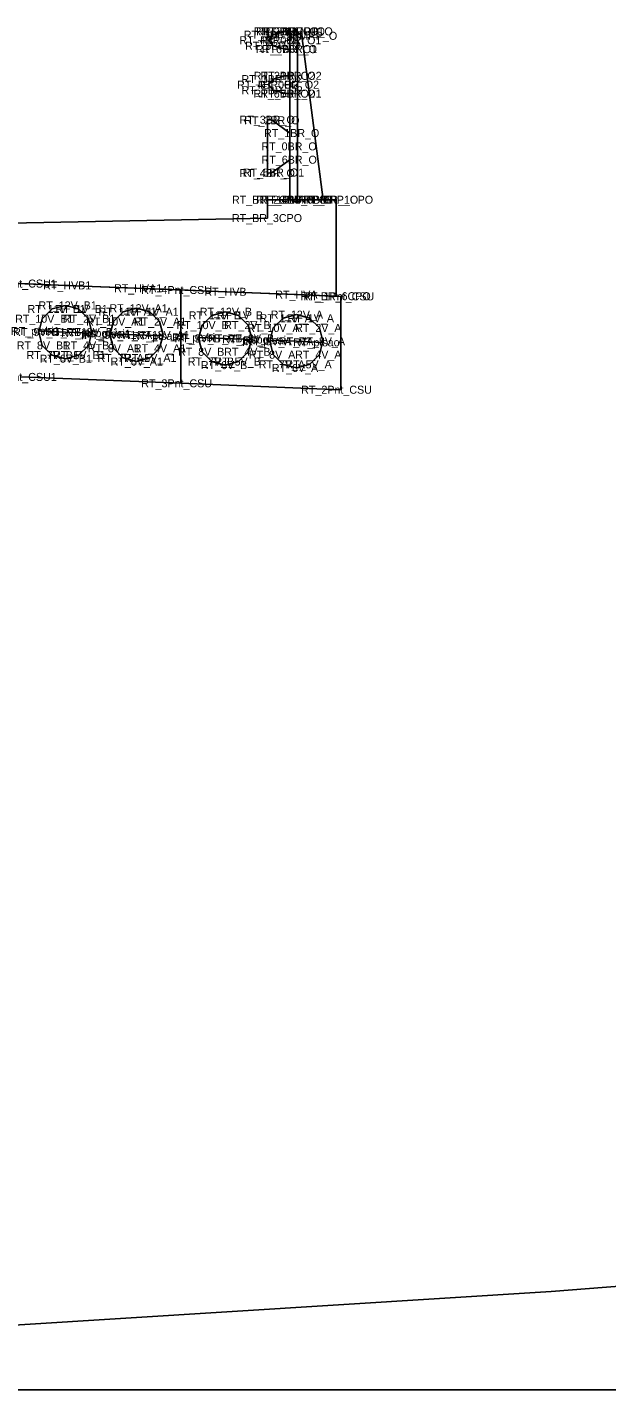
# Model space of a CAD drawing. Extents: x -26 to 1163, y -10 to 9537.
# Drawn here: x 99.37 to 110.24, y 6000 to 6025.54 of the extents above; entities that cross this region are included whole.
import ezdxf

# ---------------------------------------------------------------- set-up
doc = ezdxf.new("R2010")
doc.units = 0
for name, color, linetype in [('Exist Cross Section Cell', 7, 'Continuous'), ('Exist XS Ground Line', 7, 'Continuous'), ('Prop CMT Bridge Metal Rail', 7, 'Continuous'), ('Prop CMT Bridge Metal Rail Post', 7, 'Continuous'), ('Prop CMT Concrete Structures', 7, 'Continuous'), ('Prop CMT Corridor Surface Symbology Blue', 7, 'Continuous'), ('Scratch_Level_0', 7, 'Continuous')]:
    doc.layers.add(name, color=color, linetype=linetype)

msp = doc.modelspace()

# ---------------------------------------------------------------- linework, layer by layer
at = {"layer": 'Exist Cross Section Cell'}
msp.add_line((80, 6000), (160, 6000), dxfattribs=at)
at = {"layer": 'Exist XS Ground Line'}
msp.add_lwpolyline([(54.51, 6004.315), (62.713, 6003.678), (73.379, 6003.022), (80, 6002.975), (87.016, 6002.925), (91.312, 6001.299), (94.565, 6001.099), (97.121, 6001.084), (109.199, 6001.839), (119.662, 6002.66), (122.228, 6004.967), (124.251, 6006.909), (129.58, 6007.46), (132.249, 6006.951), (132.875, 6007.018), (147.194, 6007.634), (148.841, 6007.735), (150.67, 6007.781), (160, 6007.577)], dxfattribs=at)
at = {"layer": 'Prop CMT Bridge Metal Rail'}
for points in [[(104.293, 6025.465), (104.209, 6025.465), (103.98, 6025.402), (103.897, 6025.298)], [(104.293, 6025.298), (104.293, 6025.465)], [(103.897, 6025.298), (103.98, 6025.194), (104.209, 6025.132), (104.293, 6025.132)], [(104.293, 6025.132), (104.293, 6025.298)], [(104.293, 6024.632), (104.209, 6024.632), (103.98, 6024.569), (103.897, 6024.465)], [(103.897, 6024.465), (103.98, 6024.361), (104.209, 6024.298), (104.293, 6024.298)], [(104.293, 6024.465), (104.293, 6024.632)], [(104.293, 6024.298), (104.293, 6024.465)], [(104.293, 6023.559), (103.964, 6023.798), (103.876, 6023.809)], [(103.876, 6023.809), (103.876, 6022.809)], [(104.293, 6023.309), (104.293, 6023.559)], [(104.293, 6023.059), (104.293, 6023.309)], [(103.876, 6022.809), (103.964, 6022.819), (104.293, 6023.059)]]:
    msp.add_lwpolyline(points, dxfattribs=at)
at = {"layer": 'Prop CMT Bridge Metal Rail Post'}
for points in [[(104.293, 6022.309), (104.293, 6025.465)], [(104.293, 6025.465), (104.438, 6025.465)], [(104.438, 6025.465), (104.438, 6022.309)], [(104.438, 6025.465), (104.522, 6025.382), (104.918, 6022.309)]]:
    msp.add_lwpolyline(points, dxfattribs=at)
at = {"layer": 'Prop CMT Concrete Structures'}
for points in [[(98.375, 6020.772), (98.376, 6021.855), (103.875, 6021.965), (103.876, 6022.309), (105.166, 6022.309), (105.167, 6020.5)], [(105.167, 6020.5), (98.375, 6020.772)], [(99.25, 6020.737), (100.083, 6020.703), (101.417, 6020.65), (102.25, 6020.617)], [(102.25, 6020.617), (102.25, 6018.867)], [(102.25, 6020.617), (103.083, 6020.583), (104.417, 6020.53), (105.25, 6020.497)], [(102.25, 6018.867), (102.25, 6020.617)], [(99.583, 6019.828), (99.65, 6020.078), (99.833, 6020.261), (100.083, 6020.328)], [(100.083, 6020.328), (100.333, 6020.261), (100.516, 6020.078), (100.583, 6019.828)], [(105.25, 6020.497), (105.25, 6018.747)], [(100.917, 6019.775), (100.984, 6020.025), (101.167, 6020.208), (101.417, 6020.275)], [(101.417, 6020.275), (101.667, 6020.208), (101.85, 6020.025), (101.917, 6019.775)], [(102.583, 6019.708), (102.65, 6019.958), (102.833, 6020.141), (103.083, 6020.208)], [(103.083, 6020.208), (103.333, 6020.141), (103.516, 6019.958), (103.583, 6019.708)], [(103.917, 6019.655), (103.984, 6019.905), (104.167, 6020.088), (104.417, 6020.155)], [(104.417, 6020.155), (104.667, 6020.088), (104.85, 6019.905), (104.917, 6019.655)], [(100.583, 6019.828), (100.516, 6019.578), (100.333, 6019.395), (100.083, 6019.328), (99.833, 6019.395), (99.65, 6019.578), (99.583, 6019.828)], [(101.917, 6019.775), (101.85, 6019.525), (101.667, 6019.342), (101.417, 6019.275), (101.167, 6019.342), (100.984, 6019.525), (100.917, 6019.775)], [(103.583, 6019.708), (103.516, 6019.458), (103.333, 6019.275), (103.083, 6019.208), (102.833, 6019.275), (102.65, 6019.458), (102.583, 6019.708)], [(104.917, 6019.655), (104.85, 6019.405), (104.667, 6019.222), (104.417, 6019.155), (104.167, 6019.222), (103.984, 6019.405), (103.917, 6019.655)], [(102.25, 6018.867), (99.25, 6018.987)], [(105.25, 6018.747), (102.25, 6018.867)]]:
    msp.add_lwpolyline(points, dxfattribs=at)
at = {"layer": 'Prop CMT Corridor Surface Symbology Blue'}
for points in [[(99.593, 6019.848), (100.083, 6019.828), (100.573, 6019.809)], [(100.927, 6019.795), (101.417, 6019.775), (101.907, 6019.755)], [(102.593, 6019.728), (103.083, 6019.708), (103.573, 6019.689)], [(103.927, 6019.675), (104.417, 6019.655), (104.907, 6019.635)]]:
    msp.add_lwpolyline(points, dxfattribs=at)

# ---------------------------------------------------------------- texts
at = {"layer": 'Scratch_Level_0'}
for s, p in [('RT_3BR_O1', (103.431, 6025.327)), ('RT_2BMRP_O', (103.617, 6025.39)), ('RT_2BR_O1', (103.66, 6025.39)), ('RT_3BMRP_O', (103.763, 6025.39)), ('RT_1BR_O1', (103.786, 6025.39)), ('RT_5BMRP_O', (103.846, 6025.307)), ('RT_4BR_O1', (103.348, 6025.223)), ('RT_5BR_O', (103.456, 6025.119)), ('RT_6BR_O1', (103.657, 6025.057)), ('RT_0BR_O1', (103.738, 6025.223)), ('RT_7BR_O', (103.768, 6025.057)), ('RT_3BR_O2', (103.388, 6024.494)), ('RT_2BR_O2', (103.618, 6024.557)), ('RT_1BR_O2', (103.743, 6024.557)), ('RT_4BR_O2', (103.305, 6024.39)), ('RT_5BR_O2', (103.388, 6024.286)), ('RT_0BR_O2', (103.695, 6024.39)), ('RT_6BR_O2', (103.614, 6024.223)), ('RT_7BR_O1', (103.743, 6024.223)), ('RT_3BR_O', (103.352, 6023.734)), ('RT_2BR_O', (103.44, 6023.723)), ('RT_1BR_O', (103.811, 6023.484)), ('RT_0BR_O', (103.762, 6023.234)), ('RT_6BR_O', (103.765, 6022.984)), ('RT_4BR_O', (103.352, 6022.734)), ('RT_5BR_O1', (103.415, 6022.744)), ('RT_BR_2CPO', (103.21, 6022.234)), ('RT_1BMRP_O', (103.66, 6022.234)), ('RT_4BMRP_O', (103.763, 6022.234)), ('RT_6BMRP_O', (104.239, 6022.234)), ('RT_BR_1CPO', (104.542, 6022.234)), ('RT_BR_3CPO', (103.209, 6021.89)), ('RT_4Pnt_CSU1', (98.483, 6020.662)), ('RT_HVB1', (99.666, 6020.628)), ('RT_HVA1', (100.997, 6020.575)), ('RT_4Pnt_CSU', (101.508, 6020.542)), ('RT_HVB', (102.691, 6020.508)), ('RT_HVA', (104.022, 6020.455)), ('RT_BR_6CPO', (104.497, 6020.425)), ('RT_1Pnt_CSU', (104.551, 6020.422)), ('RT_11V_B1', (99.373, 6020.186)), ('RT_12V_B1', (99.58, 6020.253)), ('RT_1V_B1', (99.898, 6020.186)), ('RT_12V_A1', (100.911, 6020.2)), ('RT_10V_B1', (99.141, 6020.003)), ('RT_2V_B1', (100.038, 6020.003)), ('RT_10V_A1', (100.472, 6019.95)), ('RT_11V_A1', (100.704, 6020.133)), ('RT_1V_A1', (101.228, 6020.133)), ('RT_2V_A1', (101.369, 6019.95)), ('RT_11V_B', (102.398, 6020.066)), ('RT_12V_B', (102.605, 6020.133)), ('RT_1V_B', (102.922, 6020.066)), ('RT_11V_A', (103.728, 6020.013)), ('RT_12V_A', (103.936, 6020.08)), ('RT_1V_A', (104.253, 6020.013)), ('RT_ptsbi1', (99.062, 6019.773)), ('RT_9V_B1', (99.105, 6019.753)), ('RT_VB1', (99.734, 6019.753)), ('RT_ptsbo1', (100.002, 6019.734)), ('RT_3V_B1', (100.105, 6019.753)), ('RT_ptsai1', (100.394, 6019.72)), ('RT_9V_A1', (100.436, 6019.7)), ('RT_VA1', (101.065, 6019.7)), ('RT_ptsao1', (101.334, 6019.68)), ('RT_3V_A1', (101.436, 6019.7)), ('RT_ptsbi', (102.087, 6019.653)), ('RT_10V_B', (102.166, 6019.883)), ('RT_2V_B', (103.063, 6019.883)), ('RT_10V_A', (103.497, 6019.83)), ('RT_2V_A', (104.394, 6019.83)), ('RT_8V_B1', (99.172, 6019.503)), ('RT_4V_B1', (100.038, 6019.503)), ('RT_8V_A1', (100.503, 6019.45)), ('RT_4V_A1', (101.369, 6019.45)), ('RT_9V_B', (102.13, 6019.633)), ('RT_8V_B', (102.197, 6019.383)), ('RT_VB', (102.759, 6019.633)), ('RT_ptsbo', (103.026, 6019.614)), ('RT_3V_B', (103.13, 6019.633)), ('RT_ptsai', (103.419, 6019.6)), ('RT_9V_A', (103.461, 6019.58)), ('RT_VA', (104.09, 6019.58)), ('RT_ptsao', (104.359, 6019.56)), ('RT_3V_A', (104.461, 6019.58)), ('RT_7V_B1', (99.355, 6019.32)), ('RT_6V_B1', (99.601, 6019.253)), ('RT_5V_B1', (99.855, 6019.32)), ('RT_7V_A1', (100.686, 6019.267)), ('RT_6V_A1', (100.932, 6019.2)), ('RT_5V_A1', (101.186, 6019.267)), ('RT_7V_B', (102.38, 6019.2)), ('RT_6V_B', (102.626, 6019.133)), ('RT_5V_B', (102.88, 6019.2)), ('RT_4V_B', (103.063, 6019.383)), ('RT_8V_A', (103.528, 6019.33)), ('RT_7V_A', (103.711, 6019.147)), ('RT_5V_A', (104.211, 6019.147)), ('RT_4V_A', (104.394, 6019.33)), ('RT_3Pnt_CSU1', (98.483, 6018.912)), ('RT_6V_A', (103.957, 6019.08)), ('RT_3Pnt_CSU', (101.508, 6018.792)), ('RT_2Pnt_CSU', (104.508, 6018.672))]:
    msp.add_text(s, height=0.15, dxfattribs=at).set_placement(p)

doc.saveas('drawing.dxf')
